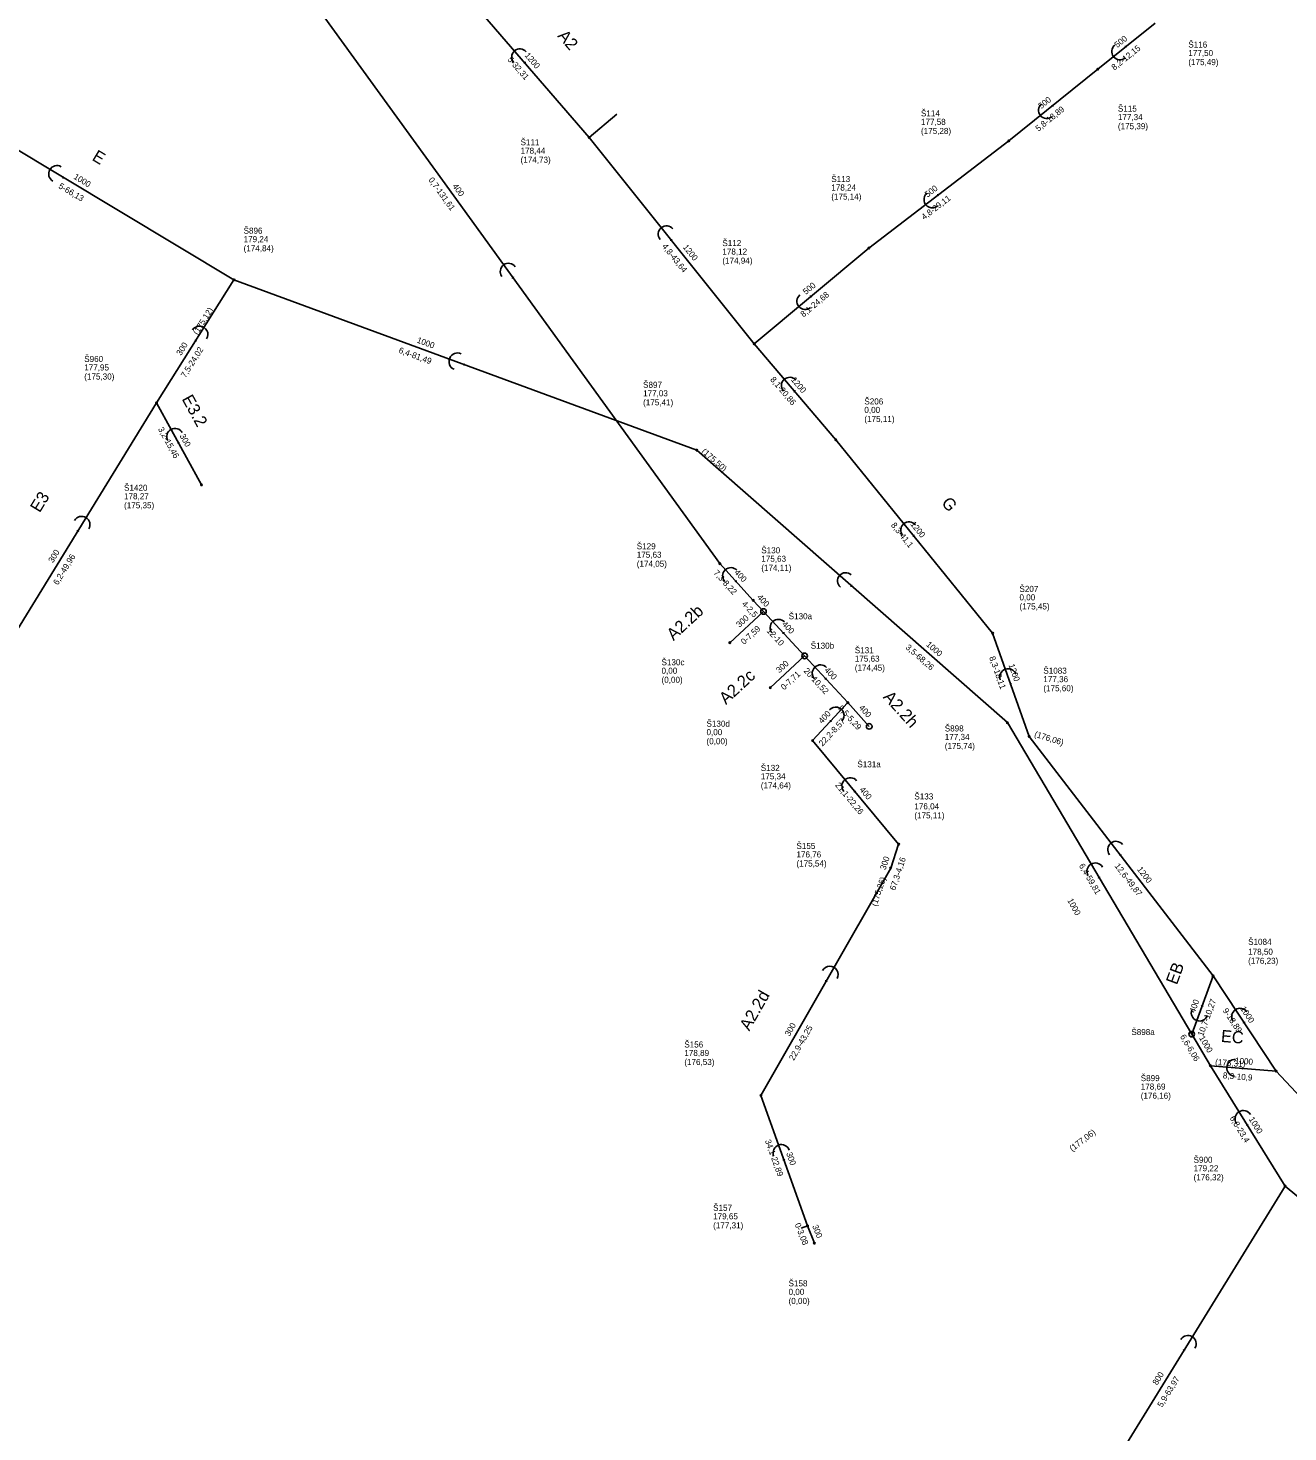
# Model space of a CAD drawing. Extents: x -548529 to -543591, y -1201432 to -1192608.
# Drawn here: x -544478.6 to -544270.5, y -1193639.2 to -1193407.2 of the extents above; entities that cross this region are included whole.
import ezdxf

# ---------------------------------------------------------------- set-up
doc = ezdxf.new("R2010")
doc.units = 0
for name, color, linetype in [('C3D_Bod-Značky', 7, 'Continuous'), ('C3D_Koridor', 7, 'Continuous'), ('C3D_Křižovatka', 7, 'Continuous'), ('C3D_Netisknutelná', 7, 'Continuous'), ('C3D_PP-zobrazeni v PR', 7, 'Continuous'), ('C3D_PR-Popisek', 7, 'Continuous'), ('C3D_SPR-Popisek', 7, 'Continuous'), ('C3D_Tlakove_potrubi_Popis', 7, 'Continuous'), ('C3D_ZPR-Formaty', 7, 'Continuous')]:
    doc.layers.add(name, color=color, linetype=linetype)

# ---------------------------------------------------------------- blocks, each defined once
blk = doc.blocks.new('100')
at = {"layer": 'Defpoints'}
blk.add_circle((0, 0), 0.127, dxfattribs=at)
blk = doc.blocks.new('101')
at = {"layer": 'Defpoints'}
blk.add_circle((0, 0), 0.463, dxfattribs=at)
blk = doc.blocks.new('91')
at = {"layer": 'Defpoints'}
blk.add_lwpolyline([(0.08, 0.14), (0.19, 0), (0.08, -0.14)], dxfattribs=at)
blk.add_arc((1.37, 0), 1.37, 270, 90, dxfattribs=at)
blk = doc.blocks.new('86')
at = {"layer": 'Defpoints'}
blk.add_lwpolyline([(0.08, 0.14), (0.19, 0), (0.08, -0.14)], dxfattribs=at)
blk.add_arc((1.37, 0), 1.37, 270, 90, dxfattribs=at)

msp = doc.modelspace()

# ---------------------------------------------------------------- linework, layer by layer
at = {"layer": 'C3D_Bod-Značky'}
for points in [[(-544364.359, -1193495.684), (-544386.722, -1193464.764), (-544410.2, -1193432.303), (-544441.49, -1193389.04)], [(-544385.936, -1193425.278), (-544407.022, -1193400.803)], [(-544292.425, -1193406.407), (-544301.914, -1193413.994)], [(-544444.64, -1193448.803), (-544501.345, -1193414.769)], [(-544301.914, -1193413.994), (-544316.622, -1193425.84)], [(-544358.677, -1193459.354), (-544385.936, -1193425.278)], [(-544316.622, -1193425.84), (-544339.728, -1193443.539)], [(-544339.728, -1193443.539), (-544358.677, -1193459.354)], [(-544457.43, -1193469.13), (-544444.64, -1193448.803)], [(-544368.162, -1193476.942), (-544444.64, -1193448.803)], [(-544345.162, -1193475.248), (-544358.677, -1193459.354)], [(-544483.57, -1193511.71), (-544457.43, -1193469.13)], [(-544449.99, -1193482.68), (-544457.43, -1193469.13)], [(-544319.278, -1193507.174), (-544345.162, -1193475.248)], [(-544316.849, -1193521.963), (-544368.162, -1193476.942)], [(-544358.834, -1193501.764), (-544364.359, -1193495.684)], [(-544357.137, -1193503.598), (-544358.834, -1193501.764)], [(-544362.708, -1193508.753), (-544357.137, -1193503.598)], [(-544350.346, -1193510.937), (-544357.137, -1193503.598)], [(-544313.241, -1193524.248), (-544319.278, -1193507.174)], [(-544356.008, -1193516.177), (-544350.346, -1193510.937)], [(-544343.204, -1193518.655), (-544350.346, -1193510.937)], [(-544349.035, -1193524.934), (-544343.204, -1193518.655)], [(-544339.67, -1193522.585), (-544343.204, -1193518.655)], [(-544286.386, -1193573.439), (-544316.849, -1193521.963)], [(-544282.855, -1193563.798), (-544313.241, -1193524.248)], [(-544334.813, -1193542.052), (-544349.035, -1193524.934)], [(-544336.124, -1193546.002), (-544334.813, -1193542.052)], [(-544357.561, -1193583.566), (-544336.124, -1193546.002)], [(-544282.855, -1193563.798), (-544286.386, -1193573.439)], [(-544272.436, -1193579.55), (-544282.855, -1193563.798)], [(-544283.3, -1193578.655), (-544286.386, -1193573.439)], [(-544272.436, -1193579.55), (-544283.3, -1193578.655)], [(-544270.96, -1193598.54), (-544283.3, -1193578.655)], [(-544242.2, -1193611.83), (-544272.436, -1193579.55)], [(-544349.87, -1193605.12), (-544357.561, -1193583.566)], [(-544304.5, -1193653.01), (-544270.96, -1193598.54)], [(-544250.944, -1193615.126), (-544270.96, -1193598.54)], [(-544348.728, -1193607.981), (-544349.87, -1193605.12)]]:
    msp.add_lwpolyline(points, dxfattribs=at)
at = {"layer": 'C3D_Koridor'}
for points in [[(-544385.936, -1193425.278), (-544381.349, -1193421.407)], [(-544349.87, -1193605.12), (-544350.93, -1193605.489)]]:
    msp.add_lwpolyline(points, dxfattribs=at)

# ---------------------------------------------------------------- block references
at = {"layer": 'C3D_PP-zobrazeni v PR'}
for name, p, xscale, yscale, rotation in [('100', (-544301.914, -1193413.994), 1.000000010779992, 1.0000000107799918, -141.00000108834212), ('100', (-544385.936, -1193425.278), 1.0000000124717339, 1.0000000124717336, 130.0000013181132), ('100', (-544316.622, -1193425.84), 1.000000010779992, 1.0000000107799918, -141.00000108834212), ('100', (-544339.728, -1193443.539), 1.000000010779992, 1.0000000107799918, -141.00000108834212), ('100', (-544444.64, -1193448.803), 1.0169562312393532, 1.016956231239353, -26.97601645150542), ('100', (-544358.677, -1193459.354), 1.0018265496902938, 1.0018265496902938, -6.078126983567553), ('100', (-544457.43, -1193469.13), 1.0000000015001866, 1.0000000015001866, 59.00000017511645), ('100', (-544345.162, -1193475.248), 1.0000000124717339, 1.0000000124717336, -49.99999868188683), ('100', (-544368.162, -1193476.942), 0.9999999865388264, 0.9999999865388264, 149.99999955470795), ('100', (-544449.99, -1193482.68), 0.9999999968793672, 0.9999999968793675, -57.99999972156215), ('100', (-544364.359, -1193495.684), 1.0000000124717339, 1.0000000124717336, 130.0000013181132), ('100', (-544358.834, -1193501.764), 1.00000000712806, 1.00000000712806, 133.00000056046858), ('101', (-544357.137, -1193503.598), 1.00000001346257, 1.0000000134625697, -91.99999990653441), ('100', (-544319.278, -1193507.174), 0.9999999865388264, 0.9999999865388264, -59.99999955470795), ('100', (-544362.708, -1193508.753), 1.00000000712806, 1.00000000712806, -136.99999943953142), ('101', (-544350.346, -1193510.937), 1.00000001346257, 1.0000000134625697, 178.0000000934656), ('100', (-544356.008, -1193516.177), 1.00000000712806, 1.00000000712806, -136.99999943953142), ('101', (-544339.67, -1193522.585), 1.0000000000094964, 1.0000000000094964, -47.99999869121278), ('100', (-544316.849, -1193521.963), 1.0000000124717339, 1.0000000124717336, 130.0000013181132), ('100', (-544313.241, -1193524.248), 0.9999999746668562, 0.999999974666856, -34.00000045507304), ('100', (-544349.035, -1193524.934), 1.000000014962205, 1.0000000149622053, 89.0000000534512), ('100', (-544334.813, -1193542.052), 1.0000000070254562, 1.0000000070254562, 118.99999892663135), ('100', (-544336.124, -1193546.002), 0.9999999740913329, 0.9999999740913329, -114.00000060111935), ('100', (-544282.855, -1193563.798), 1.000000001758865, 1.000000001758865, 125.99999933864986), ('101', (-544286.386, -1193573.439), 1.0000000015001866, 1.0000000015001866, 120.99999982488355), ('100', (-544283.3, -1193578.655), 0.9999999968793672, 0.9999999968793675, 147.99999972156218), ('100', (-544272.436, -1193579.55), 0.9999999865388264, 0.9999999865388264, -120.00000044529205), ('100', (-544357.561, -1193583.566), 1.000000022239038, 1.0000000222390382, 85.00000001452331), ('100', (-544270.96, -1193598.54), 1.0000000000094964, 1.0000000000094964, 132.0000013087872), ('100', (-544349.87, -1193605.12), 0.9999999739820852, 0.9999999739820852, 111.00000058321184), ('100', (-544348.728, -1193607.981), 1.0000000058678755, 1.0000000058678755, 111.99999900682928)]:
    msp.add_blockref(name, p, dxfattribs=dict(at, xscale=xscale, yscale=yscale, rotation=rotation))
at = {"layer": 'C3D_PP-zobrazeni v PR', "rotation": 180}
msp.add_blockref('100', (-544343.204, -1193518.655), dxfattribs=at)
at = {"layer": 'C3D_SPR-Popisek'}
for name, p, xscale, yscale, rotation in [('91', (-544396.479, -1193413.04), 1.0000000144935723, 1.0000000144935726, 130.99999910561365), ('91', (-544297.17, -1193410.2), 1.000000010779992, 1.0000000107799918, -141.00000108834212), ('91', (-544309.268, -1193419.917), 1.000000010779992, 1.0000000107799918, -141.00000108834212), ('91', (-544472.687, -1193431.969), 0.9999999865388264, 0.9999999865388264, 149.99999955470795), ('91', (-544328.175, -1193434.69), 1.000000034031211, 1.0000000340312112, -141.99999959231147), ('91', (-544372.306, -1193442.316), 1.000000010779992, 1.0000000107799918, 128.99999891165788), ('91', (-544398.461, -1193448.533), 1.000000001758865, 1.000000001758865, 125.99999933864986), ('91', (-544349.202, -1193451.446), 1.0000000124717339, 1.0000000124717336, -139.99999868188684), ('91', (-544451.035, -1193458.966), 0.9999999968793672, 0.9999999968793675, 57.99999972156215), ('91', (-544406.401, -1193462.872), 1.0296949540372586, 1.0296949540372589, 155.86620948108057), ('91', (-544351.92, -1193467.301), 1.0000000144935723, 1.0000000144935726, 130.99999910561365), ('86', (-544453.71, -1193475.905), 1.0000000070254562, 1.0000000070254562, 118.99999892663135), ('91', (-544470.5, -1193490.42), 1.0000000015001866, 1.0000000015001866, 59.00000017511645), ('91', (-544332.22, -1193491.211), 1.0000000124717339, 1.0000000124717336, 130.0000013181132), ('86', (-544361.596, -1193498.724), 1.00000000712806, 1.00000000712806, 133.00000056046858), ('91', (-544342.506, -1193499.453), 1.0000000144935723, 1.0000000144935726, 139.00000089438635), ('86', (-544353.741, -1193507.267), 1.00000000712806, 1.00000000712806, 133.00000056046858), ('86', (-544346.775, -1193514.796), 1.00000000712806, 1.00000000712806, 133.00000056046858), ('91', (-544316.259, -1193515.711), 0.9999999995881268, 0.9999999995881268, 110.00000065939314), ('86', (-544346.12, -1193521.794), 1.0000000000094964, 1.0000000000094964, 47.99999869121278), ('86', (-544341.924, -1193533.493), 1.0000000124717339, 1.0000000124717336, 130.0000013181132), ('91', (-544298.048, -1193544.023), 1.000000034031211, 1.0000000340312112, 128.00000040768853), ('91', (-544301.618, -1193547.701), 1.0000000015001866, 1.0000000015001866, 120.99999982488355), ('86', (-544346.842, -1193564.784), 1.0000000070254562, 1.0000000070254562, 61.000001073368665), ('91', (-544284.62, -1193568.618), 0.9999999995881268, 0.9999999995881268, -110.00000065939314), ('91', (-544277.646, -1193571.674), 0.9999999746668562, 0.999999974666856, 124.00000045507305), ('91', (-544277.868, -1193579.102), 1.0000000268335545, 1.0000000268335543, 176.00000028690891), ('91', (-544277.13, -1193588.598), 0.9999999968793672, 0.9999999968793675, 122.00000027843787), ('86', (-544353.715, -1193594.343), 0.9999999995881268, 0.9999999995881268, 110.00000065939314), ('91', (-544287.73, -1193625.775), 1.0000000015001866, 1.0000000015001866, 59.00000017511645)]:
    msp.add_blockref(name, p, dxfattribs=dict(at, xscale=xscale, yscale=yscale, rotation=rotation))

# ---------------------------------------------------------------- texts
at = {"layer": 'C3D_Křižovatka'}
for s, p in [('Š116', (-544286.945, -1193410.417)), ('Š115', (-544298.584, -1193421.004)), ('Š114', (-544331.122, -1193421.79)), ('Š111', (-544397.276, -1193426.558)), ('Š113', (-544345.938, -1193432.639)), ('Š896', (-544443.04, -1193441.173)), ('Š112', (-544363.937, -1193443.224)), ('Š960', (-544469.37, -1193462.37)), ('Š897', (-544377.032, -1193466.642)), ('Š206', (-544340.472, -1193469.388)), ('Š1420', (-544462.79, -1193483.65)), ('Š129', (-544378.079, -1193493.314)), ('Š130', (-544357.504, -1193493.984)), ('Š207', (-544314.848, -1193500.364)), ('Š130a', (-544352.977, -1193504.878)), ('Š130b', (-544349.336, -1193509.747)), ('Š131', (-544342.054, -1193510.495)), ('Š130c', (-544373.988, -1193512.483)), ('Š1083', (-544310.901, -1193513.878)), ('Š130d', (-544366.558, -1193522.637)), ('Š898', (-544327.189, -1193523.423)), ('Š132', (-544357.585, -1193529.944)), ('Š131a', (-544341.63, -1193529.345)), ('Š133', (-544332.213, -1193534.662)), ('Š155', (-544351.694, -1193542.842)), ('Š1084', (-544277.065, -1193558.688)), ('Š898a', (-544296.356, -1193573.589)), ('Š156', (-544370.221, -1193575.646)), ('Š899', (-544294.81, -1193581.205)), ('Š900', (-544286.08, -1193594.7)), ('Š157', (-544365.46, -1193602.64)), ('Š158', (-544352.998, -1193615.121))]:
    msp.add_text(s, height=1, dxfattribs=at).set_placement(p)
at = {"layer": 'C3D_Netisknutelná'}
for s, rotation, p in [('A2', 310.75, (-544391.26, -1193408.534)), ('E', 329.03, (-544468.211, -1193428.931)), ('E3.2', 298.77, (-544453.303, -1193468.467)), ('E3', 58.45, (-544476.733, -1193487.384)), ('G', 309.03, (-544327.836, -1193485.691)), ('A2.2b', 42.78, (-544372.01, -1193508.504)), ('A2.2c', 42.78, (-544363.343, -1193519.071)), ('A2.2h', 311.96, (-544337.48, -1193517.803)), ('EB', 69.88, (-544288.836, -1193565.397)), ('A2.2d', 60.29, (-544359.49, -1193573.018)), ('EC', 355.29, (-544281.601, -1193574.719))]:
    msp.add_text(s, height=2, rotation=rotation, dxfattribs=at).set_placement(p)
at = {"layer": 'C3D_PR-Popisek'}
for s, rotation, p in [('500', 38.64, (-544298.672, -1193410.508)), ('1200', 310.75, (-544396.66, -1193411.752)), ('500', 38.85, (-544311.242, -1193420.61)), ('1000', 329.03, (-544471.217, -1193432.032)), ('400', 305.88, (-544408.595, -1193433.324)), ('500', 37.45, (-544330.024, -1193435.224)), ('1200', 308.66, (-544370.521, -1193443.43)), ('500', 39.85, (-544350.123, -1193451.307)), ('300', 57.82, (-544453.392, -1193461.399)), ('1000', 339.8, (-544414.501, -1193459.147)), ('1200', 310.37, (-544352.664, -1193465.351)), ('300', 298.77, (-544453.643, -1193474.569)), ('1200', 309.03, (-544332.948, -1193489.2)), ('300', 58.45, (-544474.538, -1193495.655)), ('400', 312.26, (-544362.032, -1193497.2)), ('400', 312.78, (-544358.289, -1193501.318)), ('300', 42.78, (-544361.112, -1193506.319)), ('400', 312.78, (-544354.174, -1193505.765)), ('1000', 318.74, (-544330.347, -1193509.185)), ('300', 42.78, (-544354.511, -1193513.834)), ('1200', 289.47, (-544316.669, -1193512.452)), ('400', 312.78, (-544347.15, -1193513.356)), ('400', 311.96, (-544341.445, -1193519.57)), ('400', 47.12, (-544347.459, -1193522.204)), ('400', 309.72, (-544341.351, -1193533.092)), ('300', 71.64, (-544336.983, -1193546.378)), ('1200', 307.53, (-544295.47, -1193546.23)), ('1000', 298.88, (-544306.975, -1193551.335)), ('400', 69.88, (-544285.88, -1193570.022)), ('1000', 303.48, (-544278.411, -1193569.238)), ('300', 60.29, (-544352.827, -1193573.864)), ('1000', 300.61, (-544285.204, -1193574.067)), ('1000', 355.29, (-544279.27, -1193578.283)), ('1000', 301.82, (-544277.004, -1193587.484)), ('300', 289.64, (-544353.405, -1193593.13)), ('300', 291.75, (-544349.101, -1193605.172)), ('800', 58.38, (-544292.098, -1193631.529))]:
    msp.add_text(s, height=1, rotation=rotation, dxfattribs=at).set_placement(p)
at = {"layer": 'C3D_Tlakove_potrubi_Popis'}
for s, p in [('(175,49)', (-544286.945, -1193413.317)), ('177,50 ', (-544286.945, -1193411.817)), ('177,58 ', (-544331.122, -1193423.19)), ('177,34 ', (-544298.584, -1193422.404)), ('(175,28)', (-544331.122, -1193424.69)), ('(175,39)', (-544298.584, -1193423.904)), ('(174,73)', (-544397.276, -1193429.458)), ('178,44 ', (-544397.276, -1193427.958)), ('178,24 ', (-544345.938, -1193434.039)), ('(175,14)', (-544345.938, -1193435.539)), ('(174,84)', (-544443.04, -1193444.073)), ('179,24 ', (-544443.04, -1193442.573)), ('(174,94)', (-544363.937, -1193446.124)), ('178,12 ', (-544363.937, -1193444.624)), ('177,95 ', (-544469.37, -1193463.77)), ('(175,30)', (-544469.37, -1193465.27)), ('(175,41)', (-544377.032, -1193469.542)), ('177,03 ', (-544377.032, -1193468.042)), ('0,00 ', (-544340.472, -1193470.788)), ('(175,11)', (-544340.472, -1193472.288)), ('178,27 ', (-544462.79, -1193485.05)), ('(175,35)', (-544462.79, -1193486.55)), ('175,63 ', (-544378.079, -1193494.714)), ('(174,05)', (-544378.079, -1193496.214)), ('(174,11)', (-544357.504, -1193496.884)), ('175,63 ', (-544357.504, -1193495.384)), ('0,00 ', (-544314.848, -1193501.764)), ('(175,45)', (-544314.848, -1193503.264)), ('(174,45)', (-544342.054, -1193513.395)), ('175,63 ', (-544342.054, -1193511.895)), ('0,00 ', (-544373.988, -1193513.883)), ('(0,00)', (-544373.988, -1193515.383)), ('177,36 ', (-544310.901, -1193515.278)), ('(175,60)', (-544310.901, -1193516.778)), ('0,00 ', (-544366.558, -1193524.037)), ('177,34 ', (-544327.189, -1193524.823)), ('(0,00)', (-544366.558, -1193525.537)), ('(175,74)', (-544327.189, -1193526.323)), ('175,34 ', (-544357.585, -1193531.344)), ('(174,64)', (-544357.585, -1193532.844)), ('176,04 ', (-544332.213, -1193536.292)), ('(175,11)', (-544332.213, -1193537.792)), ('(175,54)', (-544351.694, -1193545.742)), ('176,76 ', (-544351.694, -1193544.242)), ('(176,23)', (-544277.065, -1193561.818)), ('178,50 ', (-544277.065, -1193560.318)), ('(176,53)', (-544370.221, -1193578.546)), ('178,89 ', (-544370.221, -1193577.046)), ('178,69 ', (-544294.81, -1193582.605)), ('(176,16)', (-544294.81, -1193584.105)), ('179,22 ', (-544286.08, -1193596.1)), ('(176,32)', (-544286.08, -1193597.6)), ('179,65 ', (-544365.46, -1193604.04)), ('(177,31)', (-544365.46, -1193605.54)), ('0,00 ', (-544352.998, -1193616.521)), ('(0,00)', (-544352.998, -1193618.021))]:
    msp.add_text(s, height=1, dxfattribs=at).set_placement(p)
at = {"layer": 'C3D_ZPR-Formaty'}
for s, rotation, p in [('8,2-12,15', 38.64, (-544299.157, -1193414.227)), ('5-32,31', 310.75, (-544399.512, -1193412.433)), ('5,8-18,89', 38.85, (-544311.716, -1193424.334)), ('5-66,13', 329.03, (-544473.715, -1193433.568)), ('0,7-131,61', 305.88, (-544412.556, -1193432.292)), ('4,8-29,11', 37.45, (-544330.587, -1193438.937)), ('4,8-43,64', 308.66, (-544373.96, -1193443.297)), ('8,1-24,68', 39.85, (-544350.528, -1193455.031)), ('  (175,12)   ', 57.82, (-544451.04, -1193458.599)), ('7,5-24,02', 57.82, (-544452.635, -1193465.07)), ('6,4-81,49', 339.8, (-544417.506, -1193460.814)), ('8,1-20,86', 310.37, (-544356.098, -1193465.314)), ('3,2-15,46', 298.77, (-544457.22, -1193473.456)), ('  (175,50)   ', 318.74, (-544368.03, -1193476.792)), ('8,3-41,1', 309.03, (-544336.149, -1193489.373)), ('6,2-49,96', 58.45, (-544473.728, -1193499.318)), ('7,3-8,22', 312.26, (-544365.471, -1193497.287)), ('4-2,5', 312.78, (-544360.808, -1193502.429)), ('0-7,59', 42.78, (-544360.332, -1193509.144)), ('12-10', 312.78, (-544356.693, -1193506.876)), ('3,5-68,26', 318.74, (-544333.752, -1193509.663)), ('8,3-18,11', 289.47, (-544319.869, -1193511.198)), ('0-7,71', 42.78, (-544353.731, -1193516.659)), ('20-10,52', 312.78, (-544350.586, -1193513.476)), ('9,5-5,29', 311.96, (-544344.88, -1193519.633)), ('22,2-8,57', 47.12, (-544347.391, -1193525.955)), ('  (176,06)   ', 342.75, (-544313.182, -1193524.057)), ('21,1-22,26', 309.72, (-544345.361, -1193532.334)), ('67,3-4,16', 71.64, (-544335.375, -1193549.762)), ('  (175,26)   ', 71.64, (-544338.688, -1193553.093)), ('6,4-59,81', 300.62, (-544305.068, -1193545.602)), ('12,6-49,87', 307.53, (-544299.185, -1193545.671)), ('10,7-10,27', 69.88, (-544284.519, -1193573.871)), ('9-18,89', 303.48, (-544281.324, -1193569.555)), ('22,9-43,25', 60.29, (-544352.132, -1193577.894)), ('6,6-6,06', 300.61, (-544288.356, -1193573.841)), ('  (176,31)   ', 355.29, (-544283.284, -1193578.456)), ('8,3-10,9', 355.29, (-544281.279, -1193580.73)), ('6,8-23,4', 301.82, (-544280.153, -1193587.323)), ('  (177,06)   ', 37.45, (-544306.71, -1193593.336)), ('34,1-22,89', 289.64, (-544356.913, -1193591.044)), ('0-3,08', 291.75, (-544352.012, -1193604.877)), ('5,9-63,97', 58.38, (-544291.291, -1193635.192))]:
    msp.add_text(s, height=1, rotation=rotation, dxfattribs=at).set_placement(p)

doc.saveas('drawing.dxf')
